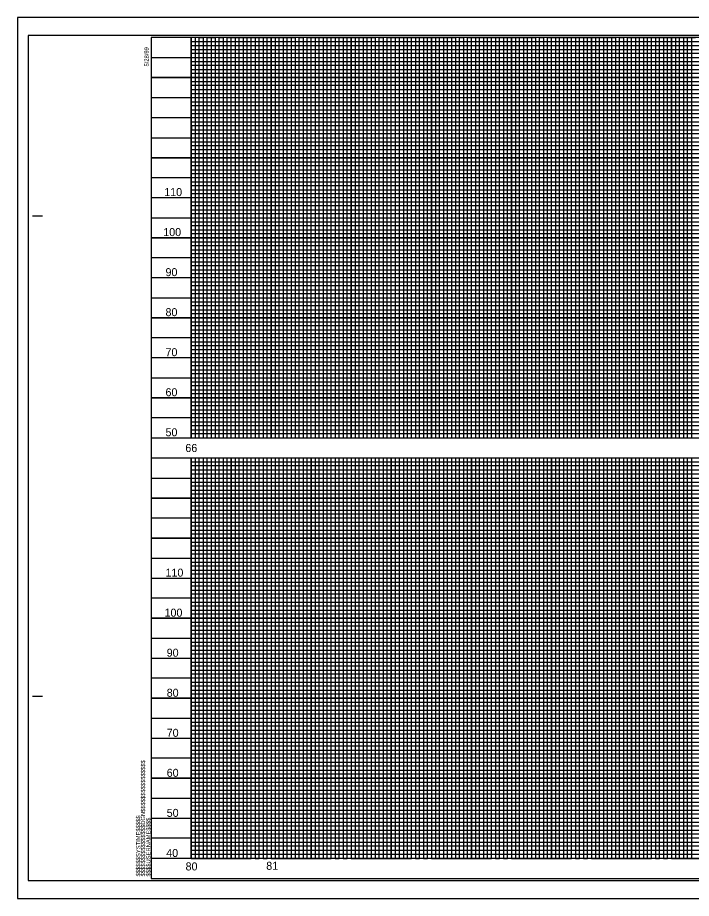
# Model space of a CAD drawing. Extents: x 2367285 to 2374385, y 803279 to 808979.
# Drawn here: x 2372701 to 2373543, y 803279 to 804379 of the extents above; entities that cross this region are included whole.
import ezdxf

# ---------------------------------------------------------------- set-up
doc = ezdxf.new("R2010")
doc.units = 0
for name, color, linetype in [('Old_Level_11', 7, 'Continuous'), ('Old_Level_12', 7, 'Continuous'), ('Old_Level_13', 7, 'Continuous'), ('Old_Level_15', 7, 'Continuous'), ('Old_Level_17', 7, 'Continuous'), ('Old_Level_19', 7, 'Continuous'), ('Old_Level_4', 7, 'Continuous'), ('Old_Level_5', 7, 'Continuous'), ('Old_Level_6', 7, 'Continuous'), ('Old_Level_63', 7, 'Continuous'), ('Old_Level_8', 7, 'Continuous'), ('Old_Level_9', 7, 'Continuous')]:
    doc.layers.add(name, color=color, linetype=linetype)

msp = doc.modelspace()

# ---------------------------------------------------------------- linework, layer by layer
at = {"layer": 'Old_Level_11'}
for p, q in [((2373368, 803829), (2373418, 803829)), ((2373468, 803829), (2373518, 803829)), ((2372868, 803329), (2372868, 803329))]:
    msp.add_line(p, q, dxfattribs=at)
for points in [[(2372918, 804354), (2372918, 803854), (2372968, 803854), (2372968, 804354), (2373018, 804354), (2373018, 803854), (2373068, 803854), (2373068, 804354), (2373118, 804354), (2373118, 803854), (2373168, 803854), (2373168, 804354), (2373218, 804354), (2373218, 803854), (2373268, 803854), (2373268, 804354), (2373318, 804354), (2373318, 803854), (2373368, 803854), (2373368, 804354), (2373418, 804354), (2373418, 803854), (2373468, 803854), (2373468, 804354), (2373518, 804354), (2373518, 803854), (2373568, 803854)], [(2372868, 804304), (2374168, 804304)], [(2374168, 804254), (2372868, 804254), (2372868, 804204), (2374168, 804204)], [(2374368, 804154), (2372868, 804154), (2372868, 804104), (2374368, 804104)], [(2374368, 804054), (2372868, 804054), (2372868, 804004), (2374368, 804004)], [(2374368, 803954), (2372868, 803954), (2372868, 803954), (2372868, 803904), (2374368, 803904)], [(2372918, 803829), (2372918, 803329), (2372968, 803329), (2372968, 803829), (2373018, 803829), (2373018, 803329), (2373068, 803329), (2373068, 803829), (2373118, 803829), (2373118, 803329), (2373168, 803329), (2373168, 803829), (2373218, 803829), (2373218, 803329), (2373268, 803329), (2373268, 803829), (2373318, 803829), (2373318, 803329), (2373368, 803329), (2373368, 803829), (2373418, 803829), (2373418, 803329), (2373468, 803329), (2373468, 803829), (2373518, 803829), (2373518, 803329), (2373568, 803329)], [(2374368, 803779), (2372868, 803779)], [(2374368, 803729), (2372868, 803729), (2372868, 803679), (2374368, 803679)], [(2374368, 803629), (2372868, 803629), (2372868, 803579), (2374368, 803579)], [(2374368, 803529), (2372868, 803529), (2372868, 803479), (2374368, 803479)], [(2374368, 803429), (2372868, 803429), (2372868, 803429), (2372868, 803379), (2374368, 803379)], [(2374368, 803329), (2372868, 803329)]]:
    msp.add_lwpolyline(points, dxfattribs=at)
at = {"layer": 'Old_Level_12'}
msp.add_line((2372868, 804329), (2374167.9, 804329), dxfattribs=at)
for points in [[(2372943, 804354), (2372943, 803854), (2372993, 803854), (2372993, 804354), (2373043, 804354), (2373043, 803854), (2373093, 803854), (2373093, 804354), (2373143, 804354), (2373143, 803854), (2373193, 803854), (2373193, 804354), (2373243, 804354), (2373243, 803854), (2373293, 803854), (2373293, 804354), (2373343, 804354), (2373343, 803854), (2373393, 803854), (2373393, 804354), (2373443, 804354), (2373443, 803854), (2373493, 803854), (2373493, 803854), (2373493, 804354), (2373543, 804354), (2373543, 803854), (2373593, 803854)], [(2374168, 804279), (2372868, 804279), (2372868, 804229), (2374168, 804229)], [(2374368, 804179), (2372868, 804179), (2372868, 804129), (2374193, 804129)], [(2374368, 804079), (2372868, 804079), (2372868, 804029), (2374368, 804029)], [(2374368, 803979), (2372868, 803979), (2372868, 803929), (2374368, 803929)], [(2374368, 803879), (2372868, 803879)], [(2372893, 803829), (2372943, 803829), (2372943, 803329), (2372993, 803329), (2372993, 803829), (2373043, 803829), (2373043, 803329), (2373093, 803329), (2373093, 803829), (2373143, 803829), (2373143, 803329), (2373193, 803329), (2373193, 803829), (2373243, 803829), (2373243, 803329), (2373293, 803329), (2373293, 803829), (2373343, 803829), (2373343, 803329), (2373393, 803329), (2373393, 803829), (2373443, 803829), (2373443, 803329), (2373493, 803329), (2373493, 803329), (2373493, 803829), (2373543, 803829), (2373543, 803329), (2373593, 803329)], [(2372868, 803804), (2374368, 803804)], [(2374368, 803754), (2372868, 803754), (2372868, 803704), (2374368, 803704)], [(2374368, 803654), (2372868, 803654), (2372868, 803604), (2374368, 803604)], [(2374368, 803554), (2372868, 803554), (2372868, 803504), (2374368, 803504)], [(2374368, 803454), (2372868, 803454), (2372868, 803404), (2374368, 803404)], [(2374368, 803354), (2372868, 803354)]]:
    msp.add_lwpolyline(points, dxfattribs=at)
at = {"layer": 'Old_Level_13'}
for p, q in [((2372918, 803854), (2372918, 804354)), ((2372968, 803854), (2372968, 804354)), ((2373018, 803854), (2373018, 804354)), ((2373068, 803854), (2373068, 804354)), ((2373118, 803854), (2373118, 804354)), ((2373168, 803854), (2373168, 804354)), ((2373218, 803854), (2373218, 804354)), ((2373268, 803854), (2373268, 804354)), ((2373318, 803854), (2373318, 804354)), ((2373368, 803854), (2373368, 804354)), ((2373418, 803854), (2373418, 804354)), ((2373468, 803854), (2373468, 804354)), ((2373518, 803854), (2373518, 804354)), ((2374167.9, 804304), (2372868, 804304)), ((2374167.9, 804254), (2372868, 804254)), ((2374168, 804204), (2372868, 804204)), ((2374368, 804154), (2372868, 804154)), ((2374368, 804104), (2372868, 804104)), ((2374368, 804054), (2372868, 804054)), ((2374368, 804004), (2372868, 804004)), ((2374368, 803954), (2372868, 803954)), ((2374368, 803904), (2372868, 803904)), ((2372868, 803829), (2374367.9, 803829)), ((2372918, 803829), (2372918, 803329)), ((2372968, 803829), (2372968, 803329)), ((2373018, 803829), (2373018, 803329)), ((2373068, 803829), (2373068, 803329)), ((2373118, 803829), (2373118, 803329)), ((2373168, 803829), (2373168, 803329)), ((2373218, 803829), (2373218, 803329)), ((2373268, 803829), (2373268, 803329)), ((2373318, 803829), (2373318, 803329)), ((2373368, 803829), (2373368, 803329)), ((2373418, 803829), (2373418, 803329)), ((2373468, 803829), (2373468, 803329)), ((2373518, 803829), (2373518, 803329)), ((2372868, 803779), (2374367.9, 803779)), ((2372868, 803729), (2374367.9, 803729)), ((2372868, 803679), (2374367.9, 803679)), ((2372868, 803629), (2374367.9, 803629)), ((2372868, 803579), (2374367.9, 803579)), ((2372868, 803529), (2374367.9, 803529)), ((2372868, 803479), (2374367.9, 803479)), ((2372868, 803429), (2374367.9, 803429)), ((2372868, 803379), (2374367.9, 803379))]:
    msp.add_line(p, q, dxfattribs=at)
at = {"layer": 'Old_Level_15'}
for p, q in [((2374385, 804379), (2372701, 804379)), ((2372701, 804379), (2372701, 803279)), ((2372701, 803279), (2374385, 803279))]:
    msp.add_line(p, q, dxfattribs=at)
at = {"layer": 'Old_Level_4'}
msp.add_lwpolyline([(2372714, 803301.4), (2374380.5, 803301.4), (2374380.5, 804356.5), (2372714, 804356.5)], close=True, dxfattribs=at)
at = {"layer": 'Old_Level_5'}
msp.add_lwpolyline([(2372918, 803829), (2374318, 803829), (2374318, 803329), (2372918, 803329)], close=True, dxfattribs=at)
at = {"layer": 'Old_Level_6'}
msp.add_lwpolyline([(2372701, 803279), (2374385, 803279), (2374385, 804379), (2372701, 804379)], close=True, dxfattribs=at)
at = {"layer": 'Old_Level_63'}
msp.add_lwpolyline([(2372918, 804192.9), (2372918, 803854), (2374318, 803854), (2374318, 804192.9)], dxfattribs=at)
at = {"layer": 'Old_Level_8'}
for p, q in [((2372918, 804349), (2374168, 804349)), ((2372918, 804344), (2372918, 804344)), ((2374168, 804344), (2372918, 804343.6)), ((2372918, 804339), (2374168, 804339)), ((2374167.9, 804219), (2372918, 804219)), ((2374168, 804214), (2372918, 804214)), ((2374168, 804209), (2372918, 804209)), ((2372918, 804199), (2374168, 804199)), ((2374168, 804194), (2372918, 804194)), ((2372918, 804189), (2374318, 804189)), ((2374318, 804169), (2372918, 804169)), ((2372918, 804164), (2374318, 804164)), ((2374318, 804144), (2372918, 804144)), ((2372918, 804139), (2374318, 804139)), ((2374318, 804119), (2372918, 804119)), ((2372918, 804114), (2374318, 804114)), ((2374318, 804109), (2372918, 804109)), ((2372918, 804099), (2374318, 804099)), ((2374318, 804094), (2372918, 804094)), ((2372918, 804089), (2374318, 804089)), ((2374318, 804084), (2372918, 804084)), ((2372918, 804074), (2374318, 804074)), ((2374318, 804069), (2372918, 804069)), ((2372918, 804064), (2374318, 804064)), ((2374318, 804059), (2372918, 804059)), ((2372918, 804049), (2374318, 804049)), ((2374318, 804044), (2372918, 804044)), ((2372918, 804039), (2374318, 804039)), ((2374318, 804034), (2372918, 804034)), ((2372918, 804024), (2374318, 804024)), ((2374318, 804019), (2372918, 804019)), ((2372918, 804014), (2374318, 804014)), ((2374318, 804009), (2372918, 804009)), ((2372918, 803999), (2374318, 803999)), ((2374318, 803994), (2372918, 803994)), ((2372918, 803989), (2374318, 803989)), ((2374318, 803984), (2372918, 803984)), ((2372918, 803974), (2374318, 803974)), ((2374318, 803969), (2372918, 803969)), ((2374318, 803964), (2372918, 803964)), ((2374318, 803959), (2372918, 803959)), ((2372918, 803949), (2374318, 803949)), ((2374318, 803944), (2372918, 803944)), ((2372918, 803939), (2374318, 803939)), ((2374318, 803934), (2372918, 803934)), ((2372918, 803924), (2374318, 803924)), ((2374318, 803919), (2372918, 803919)), ((2372918, 803914), (2374318, 803914)), ((2374318, 803909), (2372918, 803909)), ((2372918, 803899), (2374318, 803899)), ((2374318, 803894), (2372918, 803894)), ((2372918, 803889), (2374318, 803889)), ((2374318, 803884), (2372918, 803884)), ((2372918, 803874), (2374318, 803874)), ((2374318, 803869), (2372918, 803869)), ((2372918, 803864), (2374318, 803864)), ((2372918, 803824), (2374318, 803824)), ((2374318, 803819), (2372918, 803819)), ((2372918, 803814), (2374318, 803814)), ((2374318, 803809), (2372918, 803809)), ((2372918, 803799), (2374318, 803799)), ((2374318, 803794), (2372918, 803794)), ((2372918, 803789), (2374318, 803789)), ((2374318, 803784), (2372918, 803784)), ((2372918, 803774), (2374318, 803774)), ((2374318, 803769), (2372918, 803769)), ((2372918, 803764), (2374318, 803764)), ((2374318, 803759), (2372918, 803759)), ((2372918, 803749), (2374318, 803749)), ((2374318, 803744), (2372918, 803744)), ((2372918, 803739), (2374318, 803739)), ((2374318, 803734), (2372918, 803734)), ((2372918, 803724), (2374318, 803724)), ((2374318, 803719), (2372918, 803719)), ((2372918, 803714), (2374318, 803714)), ((2374318, 803709), (2372918, 803709)), ((2372918, 803699), (2374318, 803699)), ((2374318, 803694), (2372918, 803694)), ((2372918, 803689), (2374318, 803689)), ((2374318, 803684), (2372918, 803684)), ((2372918, 803674), (2374318, 803674)), ((2374318, 803669), (2372918, 803669)), ((2372918, 803664), (2374318, 803664)), ((2374318, 803659), (2372918, 803659)), ((2372918, 803649), (2374318, 803649)), ((2374318, 803644), (2372918, 803644)), ((2372918, 803639), (2374318, 803639)), ((2374318, 803634), (2372918, 803634.1)), ((2372918, 803624), (2374318, 803624)), ((2374318, 803619), (2372918, 803619)), ((2372918, 803614), (2374318, 803614)), ((2374318, 803609), (2372918, 803609)), ((2372918, 803599), (2374318, 803599)), ((2374318, 803594), (2372918, 803594)), ((2372918, 803589), (2374318, 803589)), ((2374318, 803584), (2372918, 803584)), ((2372918, 803574), (2374318, 803574)), ((2374318, 803569), (2372918, 803569)), ((2372918, 803564), (2374318, 803564)), ((2374318, 803559), (2372918, 803559)), ((2372918, 803549), (2374318, 803549)), ((2374318, 803544), (2372918, 803544)), ((2372918, 803539), (2374318, 803539)), ((2374318, 803534), (2372918, 803534)), ((2372918, 803524), (2374318, 803524)), ((2374318, 803519), (2372918, 803519)), ((2372918, 803514), (2374318, 803514)), ((2374318, 803509), (2372918, 803509)), ((2372918, 803499), (2374318, 803499)), ((2374318, 803494), (2372918, 803494)), ((2372918, 803489), (2374318, 803489)), ((2374318, 803484), (2372918, 803484)), ((2372918, 803474), (2374318, 803474)), ((2374318, 803469), (2372918, 803469)), ((2372918, 803464), (2374318, 803464)), ((2374318, 803459), (2372918, 803459)), ((2372918, 803449), (2374318, 803449)), ((2374318, 803444), (2372918, 803444)), ((2372918, 803439), (2374318, 803439)), ((2374318, 803434), (2372918, 803434)), ((2372918, 803424), (2374318, 803424)), ((2374318, 803419), (2372918, 803419)), ((2372918, 803414), (2374318, 803414)), ((2374318, 803409), (2372918, 803409)), ((2372918, 803399), (2374318, 803399)), ((2374318, 803394), (2372918, 803394)), ((2372918, 803389), (2374318, 803389)), ((2374318, 803384), (2372918, 803384)), ((2372918, 803374), (2374318, 803374)), ((2374318, 803369), (2372918, 803369)), ((2372918, 803364), (2374318, 803364)), ((2374318, 803359), (2372918, 803359)), ((2372918, 803349), (2374318, 803349)), ((2374318, 803344), (2372918, 803344)), ((2372918, 803339), (2374318, 803339)), ((2372918, 803334), (2374318, 803334))]:
    msp.add_line(p, q, dxfattribs=at)
for points in [[(2372923, 804354), (2372923, 803854), (2372928, 803854), (2372928, 804354), (2372933, 804354), (2372933, 803854), (2372938, 803854), (2372938, 804354), (2372948, 804354), (2372948, 803854), (2372953, 803854), (2372953, 804354), (2372958, 804354), (2372958, 803854), (2372963, 803854), (2372973, 803854), (2372978, 803854), (2372978, 804354), (2372983, 804354), (2372983, 803854), (2372988, 803854), (2372988, 804354), (2372998, 804354), (2372998, 803854), (2373003, 803854), (2373003, 804354), (2373008, 804354), (2373008, 803854), (2373013, 803854), (2373013, 804354), (2373023, 804354), (2373023, 803854), (2373028, 803854), (2373028, 804354), (2373033, 804354), (2373033, 803854), (2373038, 803854), (2373038, 804354), (2373048, 804354), (2373048, 803854), (2373053, 803854), (2373053, 804354), (2373058, 804354), (2373058, 803854), (2373063, 803854), (2373063, 804354), (2373073, 804354), (2373073, 803854), (2373078, 803854), (2373078, 804354), (2373083, 804354), (2373083, 803854), (2373088, 803854), (2373088, 804354), (2373098, 804354), (2373098, 803854), (2373103, 803854), (2373103, 804354), (2373108, 804354), (2373108, 803854), (2373113, 803854), (2373113, 804354), (2373123, 804354), (2373123, 803854), (2373128, 803854), (2373128, 804354), (2373133, 804354), (2373133, 803854)], [(2372963, 803854), (2372963, 804354), (2372973, 804354), (2372973, 803854)], [(2373133, 803854), (2373138, 803854), (2373138, 804354), (2373148, 804354), (2373148, 803854), (2373153, 803854), (2373153, 804354), (2373158, 804354), (2373158, 803854), (2373163, 803854), (2373163, 804354), (2373173, 804354), (2373173, 803854), (2373178, 803854), (2373178, 804354), (2373183, 804354), (2373183, 803854), (2373188, 803854), (2373188, 804354), (2373198, 804354), (2373198, 803854), (2373203, 803854), (2373203, 804354), (2373208, 804354), (2373208, 803854), (2373213, 803854), (2373213, 804354), (2373223, 804354), (2373223, 803854), (2373228, 803854), (2373228, 804354), (2373233, 804354), (2373233, 803854), (2373238, 803854), (2373238, 804354), (2373248, 804354), (2373248, 803854), (2373253, 803854), (2373253, 804354), (2373258, 804354), (2373258, 803854), (2373263, 803854), (2373263, 804354), (2373273, 804354), (2373273, 803854), (2373278, 803854), (2373278, 804354), (2373283, 804354), (2373283, 803854), (2373288, 803854), (2373288, 804354), (2373298, 804354), (2373298, 803854), (2373303, 803854), (2373303, 804354), (2373308, 804354), (2373308, 803854), (2373313, 803854), (2373313, 804354), (2373323, 804354), (2373323, 803854), (2373328, 803854), (2373328, 804354), (2373333, 804354), (2373333, 803854), (2373338, 803854), (2373338, 804354), (2373348, 804354), (2373348, 803854), (2373353, 803854), (2373353, 804354), (2373358, 804354), (2373358, 803854), (2373363, 803854), (2373363, 804354), (2373373, 804354), (2373373, 803854), (2373378, 803854), (2373378, 804354), (2373383, 804354), (2373383, 803854), (2373388, 803854), (2373388, 804354), (2373398, 804354), (2373398, 803854), (2373403, 803854), (2373403, 804354), (2373408, 804354), (2373408, 803854), (2373413, 803854), (2373413, 804354), (2373423, 804354), (2373423, 803854), (2373428, 803854), (2373428, 804354), (2373433, 804354), (2373433, 803854), (2373438, 803854), (2373438, 804354), (2373448, 804354)], [(2373448, 804354), (2373448, 803854), (2373453, 803854), (2373453, 804354), (2373458, 804354), (2373458, 803854), (2373463, 803854), (2373463, 804354), (2373473, 804354), (2373473, 803854), (2373478, 803854), (2373478, 804354), (2373483, 804354), (2373483, 803854), (2373488, 803854), (2373488, 804354), (2373498, 804354), (2373498, 803854), (2373503, 803854), (2373503, 804354), (2373508, 804354), (2373508, 803854), (2373513, 803854), (2373513, 804354), (2373523, 804354), (2373523, 803854), (2373528, 803854), (2373528, 804354), (2373533, 804354), (2373533, 803854), (2373538, 803854), (2373538, 804354), (2373548, 804354)], [(2374168, 804334), (2372918, 804334), (2372918, 804324), (2374168, 804324)], [(2374167.9, 804319), (2372918, 804319), (2372918, 804314), (2374168, 804314)], [(2374168, 804309), (2372918, 804309), (2372918, 804299), (2374168, 804299)], [(2374168, 804294), (2372918, 804294), (2372918, 804289), (2374168, 804289)], [(2374168, 804284), (2372918, 804284), (2372918, 804274), (2374168, 804274)], [(2374168, 804269), (2372918, 804269), (2372918, 804264), (2374168, 804264)], [(2374168, 804259), (2372918, 804259), (2372918, 804249), (2374168, 804249)], [(2374168, 804243.9), (2372918.1, 804243.9), (2372918.1, 804239), (2374168, 804239)], [(2374168, 804234), (2372918, 804234), (2372918, 804224), (2374168, 804224)], [(2374318, 804184), (2372918, 804184), (2372918, 804174), (2374318, 804174)], [(2374318, 804159), (2372918, 804159), (2372918, 804149), (2374318, 804149)], [(2374318, 804134), (2372918, 804134), (2372918, 804124), (2374318, 804124)], [(2374318, 803859), (2372918, 803859)], [(2372918, 803829), (2372923, 803829), (2372923, 803329), (2372928, 803329), (2372928, 803829), (2372933, 803829), (2372933, 803329), (2372938, 803329), (2372938, 803829), (2372948, 803829), (2372948, 803329), (2372953, 803329), (2372953, 803829), (2372958, 803829), (2372958, 803329), (2372963, 803329), (2372973, 803329), (2372978, 803329), (2372978, 803829), (2372983, 803829), (2372983, 803329), (2372988, 803329), (2372988, 803829), (2372998, 803829), (2372998, 803329), (2373003, 803329), (2373003, 803829), (2373008, 803829), (2373008, 803329), (2373013, 803329), (2373013, 803829), (2373023, 803829), (2373023, 803329), (2373028, 803329), (2373028, 803829), (2373033, 803829), (2373033, 803329), (2373038, 803329), (2373038, 803829), (2373048, 803829), (2373048, 803329), (2373053, 803329), (2373053, 803829), (2373058, 803829), (2373058, 803329), (2373063, 803329), (2373063, 803829), (2373073, 803829), (2373073, 803329), (2373078, 803329), (2373078, 803829), (2373083, 803829), (2373083, 803329), (2373088, 803329), (2373088, 803829), (2373098, 803829), (2373098, 803329), (2373103, 803329), (2373103, 803829), (2373108, 803829), (2373108, 803329), (2373113, 803329), (2373113, 803829), (2373123, 803829), (2373123, 803329), (2373128, 803329), (2373128, 803829), (2373133, 803829), (2373133, 803329)], [(2372963, 803329), (2372963, 803829), (2372973, 803829), (2372973, 803329)], [(2373133, 803329), (2373138, 803329), (2373138, 803829), (2373148, 803829), (2373148, 803329), (2373153, 803329), (2373153, 803829), (2373158, 803829), (2373158, 803329), (2373163, 803329), (2373163, 803829), (2373173, 803829), (2373173, 803329), (2373178, 803329), (2373178, 803829), (2373183, 803829), (2373183, 803329), (2373188, 803329), (2373188, 803829), (2373198, 803829), (2373198, 803329), (2373203, 803329), (2373203, 803829), (2373208, 803829), (2373208, 803329), (2373213, 803329), (2373213, 803829), (2373223, 803829), (2373223, 803329), (2373228, 803329), (2373228, 803829), (2373233, 803829), (2373233, 803329), (2373238, 803329), (2373238, 803829), (2373248, 803829), (2373248, 803329), (2373253, 803329), (2373253, 803829), (2373258, 803829), (2373258, 803329), (2373263, 803329), (2373263, 803829), (2373273, 803829), (2373273, 803329), (2373278, 803329), (2373278, 803829), (2373283, 803829), (2373283, 803329), (2373288, 803329), (2373288, 803829), (2373298, 803829), (2373298, 803329), (2373303, 803329), (2373303, 803829), (2373308, 803829), (2373308, 803329), (2373313, 803329), (2373313, 803829), (2373323, 803829), (2373323, 803329), (2373328, 803329), (2373328, 803829), (2373333, 803829), (2373333, 803329), (2373338, 803329), (2373338, 803829), (2373348, 803829), (2373348, 803329), (2373353, 803329), (2373353, 803829), (2373358, 803829), (2373358, 803329), (2373363, 803329), (2373363, 803829), (2373373, 803829), (2373373, 803329), (2373378, 803329), (2373378, 803829), (2373383, 803829), (2373383, 803329), (2373388, 803329), (2373388, 803829), (2373398, 803829), (2373398, 803329), (2373403, 803329), (2373403, 803829), (2373408, 803829), (2373408, 803329), (2373413, 803329), (2373413, 803829), (2373423, 803829), (2373423, 803329), (2373428, 803329), (2373428, 803829), (2373433, 803829), (2373433, 803329), (2373438, 803329), (2373438, 803829), (2373448, 803829)], [(2373448, 803829), (2373448, 803329), (2373453, 803329), (2373453, 803829), (2373458, 803829), (2373458, 803329), (2373463, 803329), (2373463, 803829), (2373473, 803829), (2373473, 803329), (2373478, 803329), (2373478, 803829), (2373483, 803829), (2373483, 803329), (2373488, 803329), (2373488, 803829), (2373498, 803829), (2373498, 803329), (2373503, 803329), (2373503, 803829), (2373508, 803829), (2373508, 803329), (2373513, 803329), (2373513, 803829), (2373523, 803829), (2373523, 803329), (2373528, 803329), (2373528, 803829), (2373533, 803829), (2373533, 803329), (2373538, 803329), (2373538, 803829), (2373548, 803829)]]:
    msp.add_lwpolyline(points, dxfattribs=at)
at = {"layer": 'Old_Level_9'}
for p, q in [((2372719.5, 804131.5), (2372732, 804131.5)), ((2372868, 803854), (2374368, 803854)), ((2372868, 803829), (2374368, 803829)), ((2372719.5, 803531.5), (2372732, 803531.5)), ((2374368, 803329), (2372868, 803329)), ((2372868, 803304), (2374368, 803304)), ((2372868, 803304), (2372868, 803304)), ((2372868, 803304), (2372868, 803304)), ((2372868, 803304), (2372868, 803304)), ((2372868, 803304), (2372868, 803304)), ((2372868, 803304), (2372868, 803304)), ((2372868, 803304), (2372868, 803304)), ((2372868, 803304), (2372868, 803304))]:
    msp.add_line(p, q, dxfattribs=at)
msp.add_lwpolyline([(2374368, 804354), (2372868, 804354), (2372868, 803304), (2374368, 803304)], close=True, dxfattribs=at)
msp.add_lwpolyline([(2372905.5, 803304), (2372905.5, 803304)], dxfattribs=at)

# ---------------------------------------------------------------- texts
at = {"layer": 'Old_Level_17'}
for s, p in [('110', (2372884.2, 804156.1)), ('110', (2372884.2, 804156.1)), ('100', (2372883, 804106.1)), ('100', (2372883, 804106.1)), ('90', (2372885.8, 804056.1)), ('90', (2372885.8, 804056.1)), ('80', (2372885.8, 804006.1)), ('80', (2372885.8, 804006.1)), ('70', (2372885.8, 803956.1)), ('70', (2372885.8, 803956.1)), ('60', (2372885.8, 803906.1)), ('60', (2372885.8, 803906.1)), ('50', (2372885.8, 803856.1)), ('50', (2372885.8, 803856.1)), ('110', (2372885.8, 803680.8)), ('110', (2372885.8, 803680.8)), ('100', (2372884.6, 803630.8)), ('100', (2372884.6, 803630.8)), ('90', (2372887.3, 803580.8)), ('90', (2372887.3, 803580.8)), ('80', (2372887.3, 803530.8)), ('80', (2372887.3, 803530.8)), ('70', (2372887.3, 803480.8)), ('70', (2372887.3, 803480.8)), ('60', (2372887.3, 803430.8)), ('60', (2372887.3, 803430.8)), ('50', (2372887.3, 803380.8)), ('50', (2372887.3, 803380.8)), ('40', (2372886.7, 803330.7))]:
    msp.add_text(s, height=10, dxfattribs=at).set_placement(p)
at = {"layer": 'Old_Level_19'}
for s, p in [('66', (2372910.6, 803836.5)), ('80', (2372910.9, 803313.9)), ('81', (2373011.7, 803314.7))]:
    msp.add_text(s, height=10, dxfattribs=at).set_placement(p)
at = {"layer": 'Old_Level_9'}
for s, p in [('5/28/99', (2372864.7, 804317.9)), ('$$$$$$$$$$$$$$$$DGN$$$$$$$$$$$$$$$$', (2372860.3, 803306.4)), ('$$$$$$SYSTIME$$$$$', (2372854.3, 803306.4)), ('$$$$USERNAME$$$$', (2372866.9, 803306.4))]:
    msp.add_text(s, height=5.25, rotation=90, dxfattribs=at).set_placement(p)

doc.saveas('drawing.dxf')
